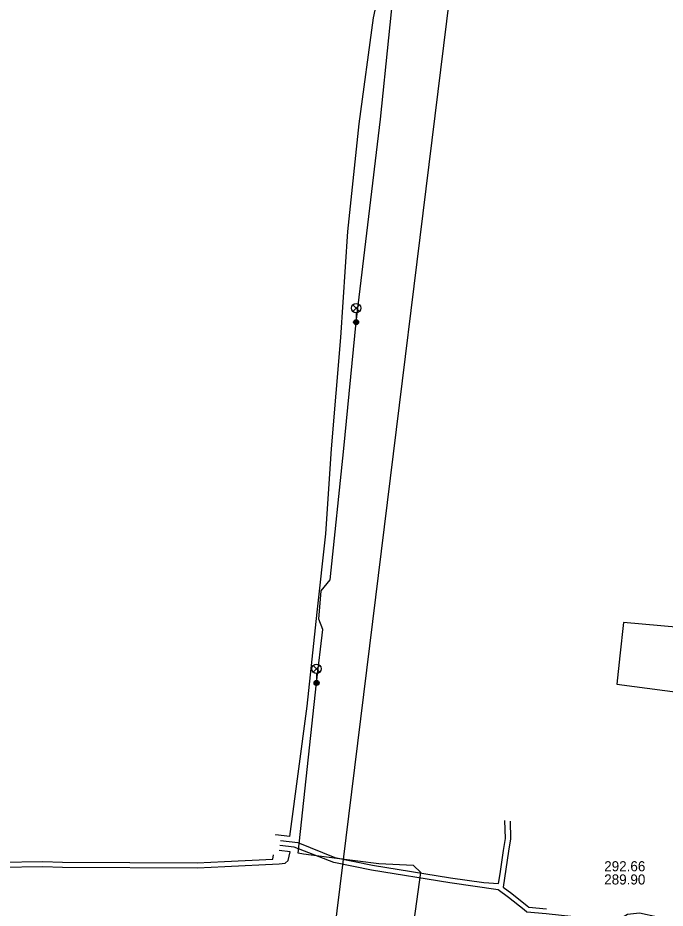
# Model space of a CAD drawing. Extents: x -595540 to -593988, y -1160850 to -1159202.
# Drawn here: x -594418.4 to -594366.9, y -1160208.9 to -1160138.2 of the extents above; entities that cross this region are included whole.
import ezdxf

# ---------------------------------------------------------------- set-up
doc = ezdxf.new("R2010")
doc.units = 0
for name, color, linetype in [('BVK-VODOVOD_trasa sítě', 7, 'Continuous'), ('CETIN_kabel podzemní', 7, 'Continuous'), ('DESTOVA-NEPROVOZOVANA_popisy', 7, 'Continuous'), ('EON-NN_kabel', 7, 'Continuous'), ('TSB_kabel VO', 7, 'Continuous'), ('TSB_lampy VO', 7, 'Continuous')]:
    doc.layers.add(name, color=color, linetype=linetype)

msp = doc.modelspace()

# ---------------------------------------------------------------- linework, layer by layer
at = {"layer": 'BVK-VODOVOD_trasa sítě'}
msp.add_lwpolyline([(-594414.304, -1160415.018), (-594414.26, -1160414.24), (-594404.1, -1160312.8), (-594403.199, -1160304.249), (-594403.197, -1160304.228), (-594393.45, -1160213.01), (-594381.18, -1160113.49), (-594372.864, -1160046.537), (-594372.845, -1160046.405)], dxfattribs=at)
at = {"layer": 'CETIN_kabel podzemní'}
msp.add_lwpolyline([(-594316.16, -1160196.13), (-594316.11, -1160195.64), (-594315.69, -1160191.86), (-594315.66, -1160191.57), (-594331.78, -1160189.93), (-594353, -1160187.77), (-594370.22, -1160186.23), (-594370.51, -1160188.88), (-594370.75, -1160191.13), (-594361.72, -1160192.31)], dxfattribs=at)
at = {"layer": 'DESTOVA-NEPROVOZOVANA_popisy'}
msp.add_line((-594371.75, -1160207.049), (-594371.75, -1160207.049), dxfattribs=at)
at = {"layer": 'EON-NN_kabel'}
for points in [[(-594388.393, -1160128.403), (-594387.987, -1160128.441), (-594388.761, -1160131.865), (-594390.11, -1160138.175), (-594391.246, -1160146.588), (-594392.151, -1160155.156), (-594392.703, -1160163.591), (-594393.469, -1160172.417), (-594393.908, -1160179.17), (-594394.591, -1160185.412), (-594395.397, -1160192.867), (-594396.783, -1160203.237), (-594397.868, -1160203.115), (-594397.871, -1160203.14)], [(-594465.382, -1160199.022), (-594456.997, -1160199.614), (-594454.896, -1160200.505), (-594453.356, -1160201.294), (-594449.626, -1160203.018), (-594446.15, -1160203.465), (-594442.09, -1160204.008), (-594438.324, -1160204.402), (-594432.789, -1160204.981), (-594429.214, -1160205.094), (-594423.139, -1160205.337), (-594416.389, -1160205.225), (-594414.812, -1160205.262), (-594404.105, -1160205.316), (-594401.935, -1160205.222), (-594398.087, -1160205.036), (-594398.044, -1160204.68)], [(-594465.411, -1160199.421), (-594457.091, -1160200.008), (-594455.066, -1160200.867), (-594453.532, -1160201.654), (-594449.738, -1160203.406), (-594446.202, -1160203.861), (-594442.138, -1160204.406), (-594438.366, -1160204.8), (-594432.817, -1160205.381), (-594429.228, -1160205.494), (-594423.143, -1160205.737), (-594416.391, -1160205.625), (-594414.818, -1160205.662), (-594404.097, -1160205.716), (-594401.917, -1160205.622), (-594397.591, -1160205.413), (-594397.107, -1160205.345), (-594396.882, -1160205.139), (-594396.707, -1160204.452), (-594397.582, -1160204.354)], [(-594397.493, -1160203.559), (-594396.109, -1160203.715), (-594393.156, -1160204.914), (-594390.182, -1160205.52), (-594383.959, -1160206.509), (-594381.327, -1160206.891), (-594380.166, -1160206.96), (-594380.03, -1160206.215), (-594379.753, -1160204.339), (-594379.599, -1160203.401), (-594379.646, -1160201.957)], [(-594379.221, -1160202.004), (-594379.197, -1160203.415), (-594379.357, -1160204.401), (-594379.781, -1160207.258), (-594379.105, -1160207.755), (-594377.867, -1160208.751), (-594377.748, -1160208.851), (-594376.332, -1160208.984)], [(-594358.169, -1160204.356), (-594358.085, -1160205.709), (-594357.991, -1160206.694), (-594357.74, -1160209.47), (-594357.552, -1160211.477), (-594357.681, -1160211.608), (-594357.785, -1160211.639), (-594358.255, -1160211.779), (-594361.714, -1160210.921), (-594366.025, -1160209.958), (-594368.935, -1160209.34), (-594369.895, -1160209.437), (-594370.827, -1160209.978), (-594371.957, -1160209.85), (-594376.372, -1160209.382), (-594377.91, -1160209.237), (-594378.121, -1160209.059), (-594379.349, -1160208.073), (-594380.179, -1160207.462), (-594384.019, -1160206.905), (-594390.254, -1160205.914), (-594393.256, -1160205.302), (-594396.411, -1160204.084), (-594397.537, -1160203.957)]]:
    msp.add_lwpolyline(points, dxfattribs=at)
at = {"layer": 'TSB_kabel VO'}
msp.add_lwpolyline([(-594386.952, -1160210.703), (-594386.332, -1160206.093), (-594386.912, -1160205.549), (-594389.665, -1160205.41), (-594393.009, -1160204.991), (-594395.653, -1160204.639), (-594396.085, -1160204.566), (-594394.616, -1160191.03), (-594394.117, -1160186.776), (-594394.45, -1160185.96), (-594394.249, -1160183.703), (-594393.549, -1160182.829), (-594392.455, -1160172.403), (-594391.473, -1160162.366), (-594389.535, -1160146.225), (-594388.22, -1160133.27)], dxfattribs=at)
at = {"layer": 'TSB_lampy VO'}
for p, q in [((-594391.738, -1160161.506), (-594391.208, -1160160.976)), ((-594391.738, -1160160.976), (-594391.208, -1160161.506)), ((-594391.738, -1160161.506), (-594391.208, -1160160.976)), ((-594391.738, -1160160.976), (-594391.208, -1160161.506)), ((-594391.473, -1160161.616), (-594391.473, -1160162.366)), ((-594391.473, -1160161.616), (-594391.473, -1160162.366)), ((-594394.881, -1160190.17), (-594394.351, -1160189.64)), ((-594394.881, -1160189.64), (-594394.351, -1160190.17)), ((-594394.881, -1160190.17), (-594394.351, -1160189.64)), ((-594394.881, -1160189.64), (-594394.351, -1160190.17)), ((-594394.616, -1160190.28), (-594394.616, -1160191.03)), ((-594394.616, -1160190.28), (-594394.616, -1160191.03))]:
    msp.add_line(p, q, dxfattribs=at)
for centre, radius in [((-594391.473, -1160161.241), 0.375), ((-594391.473, -1160161.241), 0.375), ((-594391.473, -1160162.366), 0.2), ((-594391.473, -1160162.366), 0.2), ((-594391.473, -1160162.366), 0.145), ((-594391.473, -1160162.366), 0.145), ((-594391.473, -1160162.366), 0.0876), ((-594391.473, -1160162.366), 0.0876), ((-594394.616, -1160189.905), 0.375), ((-594394.616, -1160189.905), 0.375), ((-594394.616, -1160191.03), 0.2), ((-594394.616, -1160191.03), 0.2), ((-594394.616, -1160191.03), 0.145), ((-594394.616, -1160191.03), 0.145), ((-594394.616, -1160191.03), 0.0876), ((-594394.616, -1160191.03), 0.0876)]:
    msp.add_circle(centre, radius, dxfattribs=at)

# ---------------------------------------------------------------- texts
at = {"layer": 'DESTOVA-NEPROVOZOVANA_popisy'}
for s, p in [('292.66', (-594371.75, -1160205.999)), ('289.90', (-594371.75, -1160207.049))]:
    msp.add_text(s, height=0.8, dxfattribs=at).set_placement(p)

doc.saveas('drawing.dxf')
